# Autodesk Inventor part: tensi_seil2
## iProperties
Author: MAX
Created: 2002-09
Part Number: tensi_seil2
Material: Standard
Document SubType Name: Modellieren
Designer: MAX
Control State: 0
Master: False
Checked Out: False
PropertySet Name: Design Tracking Control
Shininess: 20.0
Angle Display Precision: 2
Document Length Units: 11269
Document Angle Units: 11283
Document Time Units: 11279
Document Mass Units: 11290
Document Length Units Precision: 3
Document Angle Units Precision: 2
Compacted: False
PropertySet Name: _Private Model Information
Density: 0.0
Volumn: 0.0
Area: 0.0
PropertySet Name: Model Information
